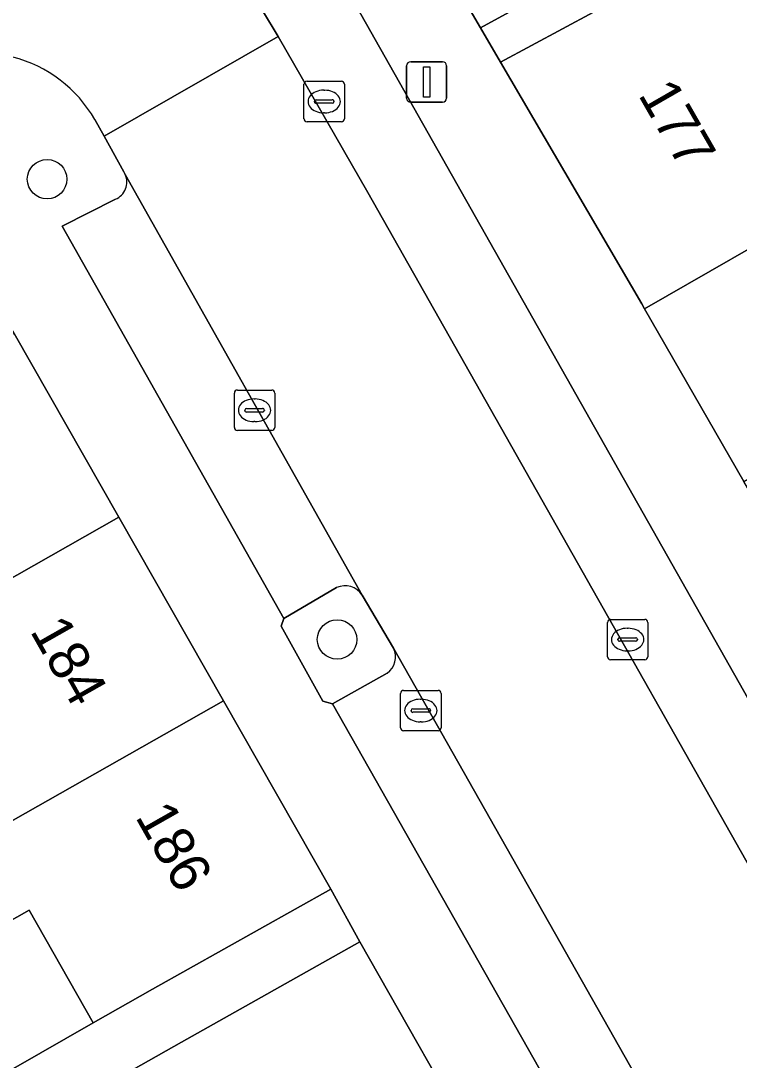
# Model space of a CAD drawing. Extents: x 159888 to 160761, y 384031 to 384750.
# Drawn here: x 160488.98 to 160506.78, y 384308.57 to 384334.29 of the extents above; entities that cross this region are included whole.
import ezdxf

# ---------------------------------------------------------------- set-up
doc = ezdxf.new("R2010")
doc.units = 0
for name, color, linetype in [('IMGEO_Boom', 7, 'Continuous'), ('IMGEO_Erf', 7, 'Continuous'), ('IMGEO_Groenvoorziening', 7, 'Continuous'), ('IMGEO_Kolk', 7, 'Continuous'), ('IMGEO_Lichtmast', 7, 'Continuous'), ('IMGEO_Pand', 7, 'Continuous'), ('IMGEO_Pand_nummerreeks', 7, 'Continuous'), ('IMGEO_Parkeervlak_open', 7, 'Continuous'), ('IMGEO_Rijbaan_lokaal_open', 7, 'Continuous'), ('IMGEO_Voetpad_open', 7, 'Continuous')]:
    doc.layers.add(name, color=color, linetype=linetype)

msp = doc.modelspace()

# ---------------------------------------------------------------- linework, layer by layer
at = {"layer": 'IMGEO_Boom'}
for centre in [(160489.633, 384330.372), (160496.816, 384318.981)]:
    msp.add_circle(centre, 0.489, dxfattribs=at)
at = {"layer": 'IMGEO_Erf'}
msp.add_lwpolyline([(160509.868, 384339.538), (160504.827, 384336.564), (160500.369, 384334.119), (160500.86, 384333.269), (160503.17, 384334.51), (160507.507, 384336.999)], dxfattribs=at)
msp.add_lwpolyline([(160487.032, 384315.964), (160485.504, 384318.66), (160484.117, 384321.107), (160479.288, 384318.371), (160478.097, 384320.473), (160477.012, 384322.387), (160475.678, 384324.741), (160470.773, 384321.422), (160473.178, 384317.676), (160469.475, 384315.595), (160472.079, 384311.028), (160474.675, 384306.475), (160478.184, 384308.475), (160480.847, 384303.804), (160490.773, 384309.494), (160489.194, 384312.28), (160484.426, 384309.578), (160484.38, 384309.552), (160482.675, 384308.586), (160481.62, 384310.447), (160483.325, 384311.413), (160482.275, 384313.267)], close=True, dxfattribs=at)
at = {"layer": 'IMGEO_Groenvoorziening'}
for points in [[(160496.803, 384320.263), (160495.494, 384319.503), (160495.432, 384319.312), (160496.463, 384317.453), (160496.707, 384317.386), (160498.055, 384318.143)], [(160498.211, 384318.768), (160497.44, 384320.079)]]:
    msp.add_lwpolyline(points, dxfattribs=at)
for centre, start, end in [((160497.018, 384319.811), 32.3516, 115.4253), ((160497.763, 384318.548), 305.8374, 26.1332)]:
    msp.add_arc(centre, 0.5, start, end, dxfattribs=at)
at = {"layer": 'IMGEO_Kolk'}
for p, q in [((160496.072, 384332.795), (160496.924, 384332.795)), ((160495.997, 384331.869), (160495.997, 384332.721)), ((160496.485, 384332.575), (160496.51, 384332.575)), ((160496.998, 384332.721), (160496.998, 384331.869)), ((160496.256, 384332.289), (160496.256, 384332.301)), ((160496.694, 384332.252), (160496.296, 384332.252)), ((160496.299, 384332.338), (160496.697, 384332.338)), ((160496.74, 384332.301), (160496.74, 384332.289)), ((160496.508, 384332.015), (160496.483, 384332.015)), ((160496.924, 384331.795), (160496.072, 384331.795)), ((160494.272, 384324.227), (160494.272, 384325.079)), ((160494.347, 384325.153), (160495.199, 384325.153)), ((160495.273, 384325.079), (160495.273, 384324.227)), ((160494.76, 384324.933), (160494.785, 384324.933)), ((160494.531, 384324.647), (160494.531, 384324.659)), ((160494.969, 384324.61), (160494.571, 384324.61)), ((160494.574, 384324.696), (160494.972, 384324.696)), ((160495.015, 384324.659), (160495.015, 384324.647)), ((160494.783, 384324.373), (160494.758, 384324.373)), ((160495.199, 384324.153), (160494.347, 384324.153)), ((160503.513, 384318.552), (160503.513, 384319.404)), ((160503.588, 384319.478), (160504.44, 384319.478)), ((160504.514, 384319.404), (160504.514, 384318.552)), ((160504.001, 384319.258), (160504.026, 384319.258)), ((160503.772, 384318.972), (160503.772, 384318.984)), ((160504.21, 384318.935), (160503.812, 384318.935)), ((160503.815, 384319.021), (160504.213, 384319.021)), ((160504.256, 384318.984), (160504.256, 384318.972)), ((160504.024, 384318.698), (160503.999, 384318.698)), ((160504.44, 384318.478), (160503.588, 384318.478)), ((160498.39, 384316.794), (160498.39, 384317.646)), ((160498.465, 384317.72), (160499.317, 384317.72)), ((160499.391, 384317.646), (160499.391, 384316.794)), ((160498.878, 384317.5), (160498.903, 384317.5)), ((160498.649, 384317.214), (160498.649, 384317.226)), ((160499.087, 384317.177), (160498.689, 384317.177)), ((160498.692, 384317.263), (160499.09, 384317.263)), ((160499.133, 384317.226), (160499.133, 384317.214)), ((160498.901, 384316.94), (160498.876, 384316.94)), ((160499.317, 384316.72), (160498.465, 384316.72))]:
    msp.add_line(p, q, dxfattribs=at)
for points in [[(160496.072, 384332.795), (160496.924, 384332.795)], [(160495.997, 384331.869), (160495.997, 384332.721)], [(160496.998, 384332.721), (160496.998, 384331.869)], [(160496.924, 384331.795), (160496.072, 384331.795)], [(160494.272, 384324.227), (160494.272, 384325.079)], [(160494.347, 384325.153), (160495.199, 384325.153)], [(160495.273, 384325.079), (160495.273, 384324.227)], [(160495.199, 384324.153), (160494.347, 384324.153)], [(160503.513, 384318.552), (160503.513, 384319.404)], [(160503.588, 384319.478), (160504.44, 384319.478)], [(160504.514, 384319.404), (160504.514, 384318.552)], [(160504.44, 384318.478), (160503.588, 384318.478)], [(160498.39, 384316.794), (160498.39, 384317.646)], [(160498.465, 384317.72), (160499.317, 384317.72)], [(160499.391, 384317.646), (160499.391, 384316.794)], [(160499.317, 384316.72), (160498.465, 384316.72)]]:
    msp.add_lwpolyline(points, dxfattribs=at)
for centre, radius, start, end in [((160496.074, 384332.719), 0.0765, 91.552, 178.448), ((160496.074, 384332.719), 0.0765, 91.552, 178.448), ((160496.922, 384332.719), 0.0765, 1.552, 88.448), ((160496.922, 384332.719), 0.0765, 1.552, 88.448), ((160496.296, 384332.298), 0.0403, 85.8775, 175.7526), ((160496.293, 384332.288), 0.0366, 178.938, 274.7102), ((160496.697, 384332.295), 0.043, 264.8664, 352.4533), ((160496.701, 384332.3), 0.0386, 1.7309, 96.639), ((160496.074, 384331.871), 0.0765, 181.552, 268.448), ((160496.074, 384331.871), 0.0765, 181.552, 268.448), ((160496.922, 384331.871), 0.0765, 271.552, 358.448), ((160496.922, 384331.871), 0.0765, 271.552, 358.448), ((160494.349, 384325.077), 0.0765, 91.552, 178.448), ((160494.349, 384325.077), 0.0765, 91.552, 178.448), ((160495.197, 384325.077), 0.0765, 1.552, 88.448), ((160495.197, 384325.077), 0.0765, 1.552, 88.448), ((160494.571, 384324.656), 0.0403, 85.8775, 175.7526), ((160494.568, 384324.646), 0.0366, 178.938, 274.7102), ((160494.972, 384324.653), 0.043, 264.8664, 352.4533), ((160494.976, 384324.658), 0.0386, 1.7309, 96.639), ((160494.349, 384324.229), 0.0765, 181.552, 268.448), ((160494.349, 384324.229), 0.0765, 181.552, 268.448), ((160495.197, 384324.229), 0.0765, 271.552, 358.448), ((160495.197, 384324.229), 0.0765, 271.552, 358.448), ((160503.59, 384319.402), 0.0765, 91.552, 178.448), ((160503.59, 384319.402), 0.0765, 91.552, 178.448), ((160504.438, 384319.402), 0.0765, 1.552, 88.448), ((160504.438, 384319.402), 0.0765, 1.552, 88.448), ((160503.812, 384318.981), 0.0403, 85.8775, 175.7526), ((160503.809, 384318.971), 0.0366, 178.938, 274.7102), ((160504.213, 384318.978), 0.043, 264.8664, 352.4533), ((160504.217, 384318.983), 0.0386, 1.7309, 96.639), ((160503.59, 384318.554), 0.0765, 181.552, 268.448), ((160503.59, 384318.554), 0.0765, 181.552, 268.448), ((160504.438, 384318.554), 0.0765, 271.552, 358.448), ((160504.438, 384318.554), 0.0765, 271.552, 358.448), ((160498.467, 384317.644), 0.0765, 91.552, 178.448), ((160498.467, 384317.644), 0.0765, 91.552, 178.448), ((160499.315, 384317.644), 0.0765, 1.552, 88.448), ((160499.315, 384317.644), 0.0765, 1.552, 88.448), ((160498.689, 384317.223), 0.0403, 85.8775, 175.7526), ((160498.686, 384317.213), 0.0366, 178.938, 274.7102), ((160499.09, 384317.22), 0.043, 264.8664, 352.4533), ((160499.094, 384317.225), 0.0386, 1.7309, 96.639), ((160498.467, 384316.796), 0.0765, 181.552, 268.448), ((160498.467, 384316.796), 0.0765, 181.552, 268.448), ((160499.315, 384316.796), 0.0765, 271.552, 358.448), ((160499.315, 384316.796), 0.0765, 271.552, 358.448)]:
    msp.add_arc(centre, radius, start, end, dxfattribs=at)
for centre, major_axis, ratio, start_param, end_param in [((160496.484, 384332.295), (-0.387, 0.002), 0.722429, 4.712389, 7.853982), ((160496.509, 384332.295), (-0.39, 0.002), 0.717154, 1.570796, 4.712389), ((160494.759, 384324.653), (-0.387, 0.002), 0.722429, 4.712389, 7.853982), ((160494.784, 384324.653), (-0.39, 0.002), 0.717154, 1.570796, 4.712389), ((160504, 384318.978), (-0.387, 0.002), 0.722429, 4.712389, 7.853982), ((160504.025, 384318.978), (-0.39, 0.002), 0.717154, 1.570796, 4.712389), ((160498.877, 384317.22), (-0.387, 0.002), 0.722429, 4.712389, 7.853982), ((160498.902, 384317.22), (-0.39, 0.002), 0.717154, 1.570796, 4.712389)]:
    msp.add_ellipse(centre, major_axis=major_axis, ratio=ratio, start_param=start_param, end_param=end_param, dxfattribs=at)
at = {"layer": 'IMGEO_Lichtmast'}
for p, q in [((160498.64, 384333.28), (160499.43, 384333.28)), ((160499.43, 384333.28), (160498.64, 384333.28)), ((160498.54, 384332.38), (160498.54, 384333.18)), ((160498.54, 384333.18), (160498.54, 384332.38)), ((160499.53, 384333.18), (160499.53, 384332.38)), ((160499.53, 384332.38), (160499.53, 384333.18)), ((160499.43, 384332.28), (160498.64, 384332.28)), ((160498.64, 384332.28), (160499.43, 384332.28))]:
    msp.add_line(p, q, dxfattribs=at)
msp.add_lwpolyline([(160498.96, 384333.155), (160499.11, 384333.155), (160499.11, 384332.405), (160498.96, 384332.405), (160498.96, 384333.155)], dxfattribs=at)
for centre, start, end in [((160498.64, 384333.18), 90, 180), ((160498.64, 384333.18), 90, 180), ((160499.43, 384333.18), 0, 90), ((160499.43, 384333.18), 360, 90), ((160498.64, 384332.38), 180, 270), ((160498.64, 384332.38), 180, 270), ((160499.43, 384332.38), 270, 0), ((160499.43, 384332.38), 270, 0)]:
    msp.add_arc(centre, 0.1, start, end, dxfattribs=at)
at = {"layer": 'IMGEO_Pand'}
for points in [[(160508.493, 384341.916), (160508.86, 384342.098), (160508.783, 384342.211), (160512.217, 384344.158), (160510.827, 384346.464), (160500.922, 384340.817), (160497.6, 384338.863), (160500.369, 384334.119), (160504.827, 384336.564), (160509.868, 384339.538)], [(160514.989, 384337.856), (160515.525, 384338.164), (160515.326, 384338.512), (160517.926, 384340.003), (160516.642, 384342.24), (160511.523, 384339.303), (160507.507, 384336.999), (160503.17, 384334.51), (160500.86, 384333.269), (160504.362, 384327.285), (160504.433, 384327.161), (160508.745, 384329.638), (160511.402, 384331.164), (160511.244, 384331.44), (160514.682, 384333.412), (160516.831, 384334.645)], [(160520.813, 384330.939), (160519.324, 384333.533), (160516.362, 384331.833), (160515.837, 384331.532), (160514.682, 384333.412), (160511.244, 384331.44), (160511.402, 384331.164), (160508.745, 384329.638), (160504.433, 384327.161), (160506.895, 384322.893), (160517.769, 384329.179), (160517.856, 384329.229)], [(160491.412, 384322.008), (160488.821, 384326.551), (160478.097, 384320.473), (160479.288, 384318.371), (160484.117, 384321.107), (160485.504, 384318.66)], [(160494.003, 384317.464), (160491.412, 384322.008), (160485.504, 384318.66), (160487.032, 384315.964), (160482.275, 384313.267), (160483.325, 384311.413)], [(160496.663, 384312.799), (160494.003, 384317.464), (160483.325, 384311.413), (160481.62, 384310.447), (160482.675, 384308.586), (160484.38, 384309.552), (160484.426, 384309.578), (160489.194, 384312.28), (160490.773, 384309.494), (160492.245, 384310.328)], [(160493.639, 384302.061), (160500.525, 384305.972), (160497.383, 384311.495), (160492.966, 384309.015), (160491.956, 384308.446), (160490.486, 384307.61), (160492.415, 384304.215), (160478.853, 384296.511), (160477.633, 384295.818), (160477.473, 384295.727), (160478.696, 384293.573), (160478.813, 384293.639), (160480.077, 384294.357), (160480.302, 384294.485), (160487.448, 384298.544)]]:
    msp.add_lwpolyline(points, close=True, dxfattribs=at)
at = {"layer": 'IMGEO_Parkeervlak_open'}
for points in [[(160495.63, 384337.604), (160493.802, 384336.483), (160495.358, 384333.901), (160497.578, 384330.042), (160511.635, 384305.223)], [(160511.856, 384305.865), (160513.168, 384306.618), (160495.63, 384337.604)], [(160497.44, 384320.079), (160491.567, 384330.488)], [(160491.327, 384329.879), (160490.011, 384329.209), (160495.494, 384319.503), (160496.803, 384320.263)], [(160516.314, 384286.833), (160498.211, 384318.768)], [(160498.055, 384318.143), (160496.707, 384317.386), (160514.376, 384286.229), (160515.684, 384287.006)]]:
    msp.add_lwpolyline(points, dxfattribs=at)
for centre, radius, start, end in [((160491.157, 384330.298), 0.452, 292.1391, 24.8432), ((160497.018, 384319.811), 0.5, 32.3516, 115.4253), ((160497.763, 384318.548), 0.5, 305.8374, 26.1332)]:
    msp.add_arc(centre, radius, start, end, dxfattribs=at)
at = {"layer": 'IMGEO_Rijbaan_lokaal_open'}
msp.add_lwpolyline([(160490.817, 384331.848), (160491.044, 384331.438), (160495.358, 384333.901), (160493.802, 384336.483)], dxfattribs=at)
msp.add_lwpolyline([(160495.358, 384333.901), (160491.044, 384331.438), (160491.531, 384330.552), (160491.567, 384330.488), (160497.44, 384320.079), (160498.211, 384318.768), (160516.314, 384286.833), (160516.788, 384285.989), (160521.189, 384288.49), (160520.799, 384289.095), (160512.39, 384303.911), (160511.635, 384305.223), (160497.578, 384330.042)], close=True, dxfattribs=at)
msp.add_arc((160487.97, 384330.217), 3.281, 29.8057, 121.4605, dxfattribs=at)
at = {"layer": 'IMGEO_Voetpad_open'}
for points in [[(160500.86, 384333.269), (160500.369, 384334.119), (160497.6, 384338.863), (160495.386, 384342.739), (160478.279, 384371.695), (160476.896, 384370.172), (160479.501, 384365.688), (160478.05, 384364.684), (160477.94, 384364.382), (160484.707, 384354.609), (160491.01, 384344.965), (160492.01, 384343.385), (160494.523, 384339.39), (160495.63, 384337.604), (160513.168, 384306.618), (160513.465, 384306.524), (160514.462, 384304.792), (160514.368, 384304.478), (160522.325, 384290.477), (160521.016, 384289.724)], [(160538.343, 384292.029), (160536.542, 384295.581), (160536.236, 384296.185), (160533.646, 384295.03), (160525.5, 384290.386), (160522.681, 384295.336), (160519.831, 384300.342), (160517.105, 384305.128), (160516.833, 384305.606), (160515.819, 384305.009), (160515.66, 384305.306), (160512.421, 384311.338), (160509.525, 384316.732), (160509.071, 384317.578), (160509.76, 384317.924), (160509.399, 384318.55), (160506.895, 384322.893), (160504.433, 384327.161), (160504.362, 384327.285), (160500.86, 384333.269)], [(160486.257, 384333.016), (160485.596, 384332.555), (160485.451, 384332.462), (160486.16, 384331.218), (160488.821, 384326.551), (160491.412, 384322.008), (160494.003, 384317.464), (160496.663, 384312.799), (160497.383, 384311.495), (160500.525, 384305.972), (160503.615, 384300.54), (160506.705, 384295.108), (160509.796, 384289.676), (160512.886, 384284.244), (160515.577, 384279.514), (160516.041, 384278.668), (160533.512, 384250), (160556.908, 384211.788), (160559.072, 384207.22), (160560.667, 384202.459), (160562.778, 384192.752), (160563.394, 384187.766), (160564.326, 384177.793)], [(160491.567, 384330.488), (160491.531, 384330.552), (160491.044, 384331.438), (160490.817, 384331.848)], [(160515.684, 384287.006), (160514.376, 384286.229), (160496.707, 384317.386), (160496.463, 384317.453), (160495.432, 384319.312), (160495.494, 384319.503), (160490.011, 384329.209), (160491.327, 384329.879)], [(160484.852, 384282.694), (160483.67, 384284.774), (160478.813, 384293.639), (160478.696, 384293.573), (160477.473, 384295.727), (160477.633, 384295.818), (160475.868, 384299.074), (160490.486, 384307.61), (160491.956, 384308.446), (160492.966, 384309.015), (160497.383, 384311.495), (160496.663, 384312.799), (160492.245, 384310.328), (160490.773, 384309.494), (160480.847, 384303.804), (160475.499, 384300.755)]]:
    msp.add_lwpolyline(points, dxfattribs=at)
for centre, radius, start, end in [((160487.97, 384330.217), 3.281, 29.8057, 121.4605), ((160491.157, 384330.298), 0.452, 292.1391, 24.8432)]:
    msp.add_arc(centre, radius, start, end, dxfattribs=at)

# ---------------------------------------------------------------- texts
at = {"layer": 'IMGEO_Pand_nummerreeks'}
for s, rotation, p in [('177', 299.8738, (160504.26, 384332.466)), ('184', 299.5415, (160489.197, 384319.193)), ('186', 299.5415, (160491.803, 384314.595))]:
    msp.add_text(s, height=1, rotation=rotation, dxfattribs=at).set_placement(p)

doc.saveas('drawing.dxf')
